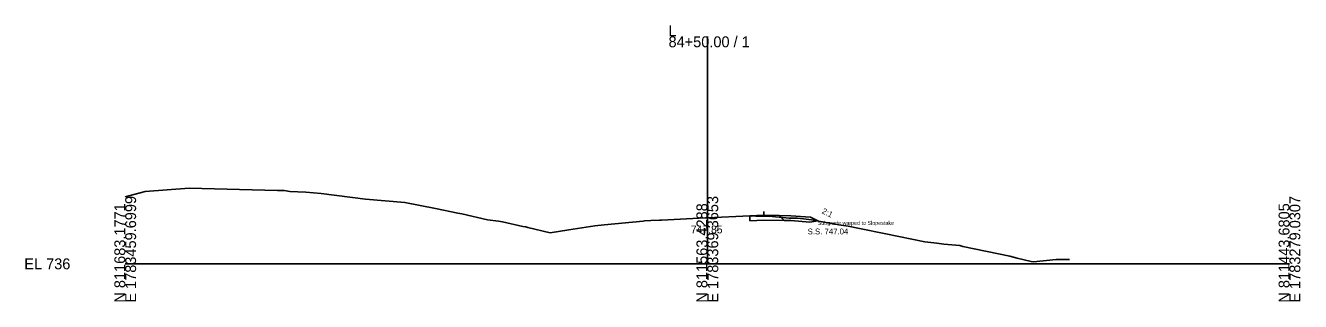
# Model space of a CAD drawing. Extents: x -26 to 7903, y -10 to 9573.
# Drawn here: x 4974.3 to 5302.8, y 5490.3 to 5561.4 of the extents above; entities that cross this region are included whole.
import ezdxf

# ---------------------------------------------------------------- set-up
doc = ezdxf.new("R2010")
doc.units = 0
for name, color, linetype in [('Exist Cross Section Cell', 7, 'Continuous'), ('Exist XS Center Line Elevation Label', 7, 'Continuous'), ('Exist XS Ground Line', 7, 'Continuous'), ('Prop XS Dump Level', 7, 'Continuous'), ('Prop XS Earthwork Shape', 7, 'Continuous'), ('Prop XS EOT Tick Mark', 7, 'Continuous'), ('Prop XS Finish Grade', 7, 'Continuous'), ('Prop XS Finish Grade Paved Shoulder', 7, 'Continuous'), ('Prop XS Finish Grade Pavement', 7, 'Continuous'), ('Prop XS Pvmt Edge Slope', 7, 'Continuous'), ('Prop XS Side Slope Text', 7, 'Continuous'), ('Prop XS SS Elevation Text', 7, 'Continuous'), ('Prop XS Subgrade Earthwork', 7, 'Continuous'), ('Scratch_Level_3', 7, 'Continuous'), ('Scratch_Level_6', 7, 'Continuous')]:
    doc.layers.add(name, color=color, linetype=linetype)

msp = doc.modelspace()

# ---------------------------------------------------------------- linework, layer by layer
at = {"layer": 'Exist Cross Section Cell'}
for p, q in [((5150, 5500), (5150, 5558.59)), ((5000, 5500), (5150, 5500)), ((5150, 5500), (5300, 5500))]:
    msp.add_line(p, q, dxfattribs=at)
at = {"layer": 'Exist XS Ground Line'}
for p, q in [((5005.18, 5518.6), (5016.51, 5519.53)), ((5016.51, 5519.53), (5039.21, 5518.87)), ((5000, 5517.23), (5005.18, 5518.6)), ((5039.21, 5518.87), (5040.95, 5518.89)), ((5040.95, 5518.89), (5042.42, 5518.6)), ((5042.42, 5518.6), (5046.56, 5518.46)), ((5046.56, 5518.46), (5050.51, 5518.15)), ((5050.51, 5518.15), (5061.94, 5516.67)), ((5061.94, 5516.67), (5072.08, 5515.81)), ((5072.08, 5515.81), (5079.95, 5514.22)), ((5079.95, 5514.22), (5085.7, 5513.09)), ((5085.7, 5513.09), (5086.76, 5512.85)), ((5086.76, 5512.85), (5093.39, 5511.35)), ((5093.39, 5511.35), (5096.19, 5510.98)), ((5096.19, 5510.98), (5096.73, 5510.93)), ((5096.73, 5510.93), (5097.19, 5510.8)), ((5097.19, 5510.8), (5102.46, 5509.62)), ((5102.46, 5509.62), (5103.25, 5509.5)), ((5103.25, 5509.5), (5103.71, 5509.4)), ((5117.62, 5509.31), (5121, 5509.82)), ((5121, 5509.82), (5123.45, 5510.02)), ((5123.45, 5510.02), (5133.44, 5511.01)), ((5133.44, 5511.01), (5133.82, 5511.05)), ((5133.82, 5511.05), (5135.42, 5511.14)), ((5135.42, 5511.14), (5137.65, 5511.27)), ((5137.65, 5511.27), (5138.21, 5511.29)), ((5138.21, 5511.29), (5149.52, 5511.83)), ((5149.52, 5511.83), (5150, 5511.85)), ((5150, 5511.85), (5160.96, 5512.34)), ((5160.96, 5512.34), (5162.53, 5512.32)), ((5162.53, 5512.32), (5165.41, 5512.29)), ((5165.41, 5512.29), (5165.83, 5512.25)), ((5165.83, 5512.25), (5171.1, 5511.77)), ((5171.1, 5511.77), (5173.19, 5511.73)), ((5173.19, 5511.73), (5174.78, 5511.63)), ((5174.78, 5511.63), (5176.88, 5511.32)), ((5176.88, 5511.32), (5183.87, 5510.09)), ((5183.87, 5510.09), (5186.29, 5509.68)), ((5186.29, 5509.68), (5189.23, 5509.08)), ((5103.71, 5509.4), (5109.52, 5508.03)), ((5109.52, 5508.03), (5114.27, 5508.8)), ((5114.27, 5508.8), (5117.62, 5509.31)), ((5189.23, 5509.08), (5195.96, 5507.7)), ((5195.96, 5507.7), (5206.08, 5505.67)), ((5206.08, 5505.67), (5209.15, 5505.31)), ((5209.15, 5505.31), (5209.76, 5505.21)), ((5209.76, 5505.21), (5210.96, 5505.11)), ((5210.96, 5505.11), (5215.04, 5504.7)), ((5215.04, 5504.7), (5215.85, 5504.46)), ((5215.85, 5504.46), (5227.92, 5501.94)), ((5227.92, 5501.94), (5229.87, 5501.5)), ((5229.87, 5501.5), (5233.46, 5500.64)), ((5233.46, 5500.64), (5234.08, 5500.55)), ((5234.08, 5500.55), (5239.9, 5501.08)), ((5239.9, 5501.08), (5243.29, 5501.14))]:
    msp.add_line(p, q, dxfattribs=at)
at = {"layer": 'Prop XS Dump Level'}
msp.add_line((5160.98, 5512.29), (5164.54, 5512.43), dxfattribs=at)
at = {"layer": 'Prop XS Earthwork Shape'}
msp.add_lwpolyline([(5171.48, 5511.15), (5176.44, 5510.75), (5178.45, 5511.04), (5176.88, 5511.32), (5174.78, 5511.63), (5173.19, 5511.73), (5171.1, 5511.77), (5165.83, 5512.25), (5165.41, 5512.29), (5162.53, 5512.32), (5160.96, 5512.34), (5160.96, 5511.09), (5164.55, 5511.25), (5169.8, 5511.18)], close=True, dxfattribs=at)
at = {"layer": 'Prop XS EOT Tick Mark'}
msp.add_line((5164.54, 5512.5), (5164.54, 5513.5), dxfattribs=at)
at = {"layer": 'Prop XS Finish Grade'}
for p, q in [((5168.54, 5512.44), (5171.54, 5512.4)), ((5171.54, 5512.4), (5176.54, 5512)), ((5176.54, 5512), (5178.45, 5511.04))]:
    msp.add_line(p, q, dxfattribs=at)
at = {"layer": 'Prop XS Finish Grade Paved Shoulder'}
msp.add_line((5164.54, 5512.5), (5168.54, 5512.44), dxfattribs=at)
at = {"layer": 'Prop XS Finish Grade Pavement'}
msp.add_line((5160.96, 5512.34), (5164.54, 5512.5), dxfattribs=at)
at = {"layer": 'Prop XS Pvmt Edge Slope'}
msp.add_line((5168.54, 5512.44), (5169.8, 5511.18), dxfattribs=at)
at = {"layer": 'Prop XS Subgrade Earthwork'}
for p, q in [((5160.96, 5511.09), (5160.96, 5512.34)), ((5160.96, 5511.09), (5164.55, 5511.25)), ((5164.55, 5511.25), (5169.8, 5511.18)), ((5169.8, 5511.18), (5171.48, 5511.15)), ((5171.48, 5511.15), (5176.44, 5510.75)), ((5176.44, 5510.75), (5178.45, 5511.04))]:
    msp.add_line(p, q, dxfattribs=at)
at = {"layer": 'Scratch_Level_3'}
for p, q in [((5171.54, 5512.4), (5168.54, 5512.44)), ((5168.54, 5512.44), (5169.8, 5511.18)), ((5169.8, 5511.18), (5171.48, 5511.15)), ((5171.48, 5511.15), (5176.44, 5510.75)), ((5176.54, 5512), (5171.54, 5512.4)), ((5176.44, 5510.75), (5178.45, 5511.04)), ((5178.45, 5511.04), (5176.54, 5512))]:
    msp.add_line(p, q, dxfattribs=at)
at = {"layer": 'Scratch_Level_6'}
msp.add_lwpolyline([(5160.96, 5511.09), (5160.96, 5512.34), (5162.53, 5512.32), (5165.41, 5512.29), (5165.83, 5512.25), (5171.1, 5511.77), (5173.19, 5511.73), (5174.78, 5511.63), (5176.88, 5511.32), (5178.45, 5511.04), (5176.44, 5510.75), (5171.48, 5511.15), (5169.8, 5511.18), (5164.55, 5511.25)], close=True, dxfattribs=at)

# ---------------------------------------------------------------- texts
at = {"layer": 'Exist Cross Section Cell'}
for s, p in [('L', (5140, 5558.59)), ('84+50.00 / 1', (5140, 5555.79)), ('EL 736', (4974, 5498.6))]:
    msp.add_text(s, height=2.8, dxfattribs=at).set_placement(p)
for s, p in [('E 1783459.6999', (5002.8, 5490)), ('E 1783369.3653', (5152.8, 5490)), ('E 1783279.0307', (5302.8, 5490)), ('N 811683.1771', (5000, 5490)), ('N 811563.4288', (5150, 5490)), ('N 811443.6805', (5300, 5490))]:
    msp.add_text(s, height=2.8, rotation=90, dxfattribs=at).set_placement(p)
at = {"layer": 'Exist XS Center Line Elevation Label'}
msp.add_text('747.85', height=2, dxfattribs=at).set_placement((5145.74, 5507.85))
at = {"layer": 'Prop XS Dump Level'}
for s, height, p in [('Eop', 0.3, (5160.96, 5512.04)), ('Case4', 0.04, (5176.54, 5511.96)), ('Subgrade warped to Slopestake', 1, (5178.45, 5510.04))]:
    msp.add_text(s, height=height, dxfattribs=at).set_placement(p)
at = {"layer": 'Prop XS Side Slope Text'}
msp.add_text('2:1', height=1.5, rotation=333.4349, dxfattribs=at).set_placement((5179.37, 5513.1))
at = {"layer": 'Prop XS SS Elevation Text'}
msp.add_text('S.S. 747.04', height=1.5, dxfattribs=at).set_placement((5175.84, 5507.59))

doc.saveas('drawing.dxf')
